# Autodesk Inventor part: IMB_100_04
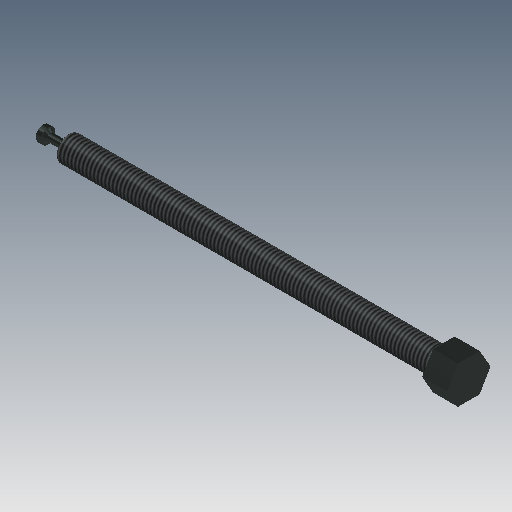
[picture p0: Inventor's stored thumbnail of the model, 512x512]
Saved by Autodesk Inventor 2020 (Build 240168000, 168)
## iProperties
Created: 2011-02
Part Number: IMB_100_04
Document SubType Name: Modeling
Designer: F.Stasiak
Density: 7.85 g/cm^3
Material: Stal
Description: Śruba dociskowa
Appearance: Brąz armatni — polerowany
Mass: 108.725 g
Surface Area: 57.5926 cm^2
Volume: 13.8504 cm^3
Manager: www.cadconsulting.pl
Company: Fabian Stasiak CAD Consulting
Author: F.Stasiak
Subject: Zbiór ćwiczeń. Autodesk Inventor 2020. Kurs podstawowy
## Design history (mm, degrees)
sketch "Szkic1"
  geometry: L1 (0, 0)-(160, 0); L2 (160, 0)-(160, 5); L3 (160, 5)-(10, 5); L4 (10, 5)-(10, 1.5); L5 (10, 1.5)-(2, 1.5); L6 (2, 1.5)-(2, 3); L7 (2, 3)-(0, 3); L8 (0, 3)-(0, 0)
  constraints: 17 end point, 3 parallel, 3 perpendicular, 1 horizontal
  dimensions: "d8" = 160 distance of L1.start L1.end; "d10" = 150 distance of L2.end L3.end; "d12" = 8 distance of L4.end L5.end; "d14" = 2 distance of L6.end L7.end; "d15" = 6 diameter of L7 L1; "d16" = 3 diameter of L5 L1; "d17" = 10 diameter of L3 L1
revolve "Obrót1" sketch "Szkic1" stored, may be unused: angle "d18" = 90 deg
sketch "Szkic2"
  geometry: L1 (4.33, 7.5)-(8.66, 0); L2 (8.66, 0)-(4.33, -7.5); L3 (4.33, -7.5)-(-4.33, -7.5); L4 (-4.33, -7.5)-(-8.66, 0); L5 (-8.66, 0)-(-4.33, 7.5); L6 (-4.33, 7.5)-(4.33, 7.5); C1 r 5 at (0, 0) reference; 1 further point
  constraints: 12 end point, 1 coincident, 13 other
  dimensions: "d19" = 15 distance between parallel lines of L6 L3
extrude "Wyciągnięcie proste1" join sketch "Szkic2" distance "d20" = 10; taper "d21" = 0 deg
chamfer "Faza1" distance "d22" = 0.5; stored, may be unused: second distance "d23" = 2, angle "d24" = 45 deg
chamfer "Faza2" distance "d25" = 1; stored, may be unused: second distance "d26" = 2, angle "d27" = 45 deg
feature "Gwint1" dims "d28" = 10, "d29" = 0
node "Bryła1"
